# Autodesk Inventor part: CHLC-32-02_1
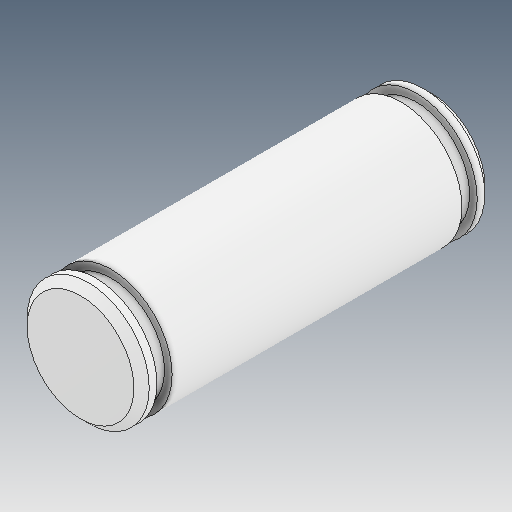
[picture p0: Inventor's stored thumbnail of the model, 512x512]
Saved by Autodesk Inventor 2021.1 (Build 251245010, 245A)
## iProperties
Created: 2021-05
Part Number: CHLC-32-02_1
Material: Ogólny
Document SubType Name: Modeling
Designer: user
Density: 1 g/cm^3
Appearance: Domyślna
Author: user
Revision Number: ÈÎºÎ
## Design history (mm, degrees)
feature "ÊäÈë1"
node "Bryła1"
